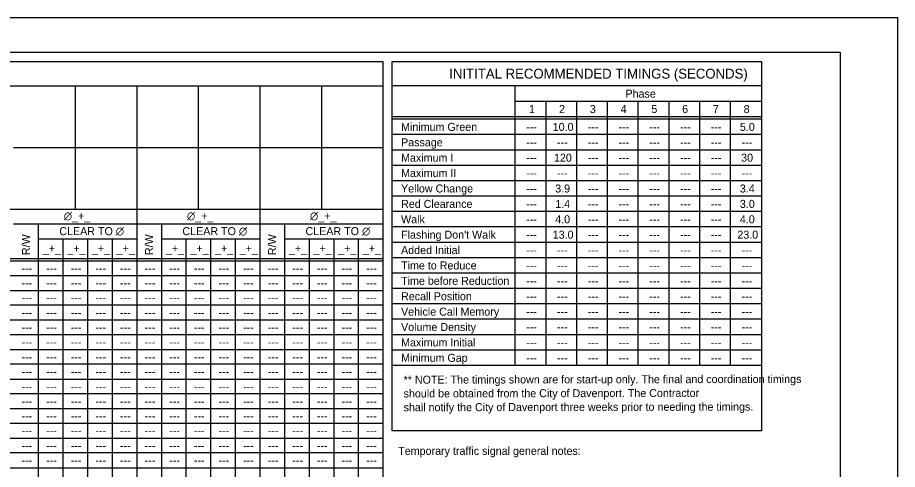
# Model space of a CAD drawing. Extents: x 10040 to 81668, y 7194 to 11018.
# Drawn here: x 11931 to 13360, y 9266 to 10000 of the extents above; entities that cross this region are included whole.
import ezdxf

# ---------------------------------------------------------------- set-up
doc = ezdxf.new("R2010")
doc.units = 0
for name, color, linetype in [('dsnCellElements', 7, 'Continuous'), ('dsnStdTable', 7, 'Continuous'), ('Level 3', 7, 'Continuous'), ('Level 4', 7, 'Continuous'), ('wetSpecialNote', 7, 'Continuous')]:
    doc.layers.add(name, color=color, linetype=linetype)

msp = doc.modelspace()

# ---------------------------------------------------------------- linework, layer by layer
at = {"layer": 'dsnCellElements'}
msp.add_lwpolyline([(10039.6, 10000), (13360.5, 10000), (13360.5, 7806.6), (10039.6, 7806.6)], close=True, dxfattribs=at)
at = {"layer": 'Level 3'}
msp.add_lwpolyline([(10132.5, 9944), (13267.5, 9944), (13267.5, 7924), (10132.5, 7924)], close=True, dxfattribs=at)
msp.add_lwpolyline([(10132.5, 9944), (13267.5, 9944), (13267.5, 7924), (10132.5, 7924)], close=True, dxfattribs=at)
at = {"layer": 'Level 4'}
for p, q in [((10664.5, 9889), (12524.5, 9889)), ((12124.5, 9889), (12124.5, 8885)), ((12124.5, 9889), (12124.5, 8885)), ((12324.5, 9889), (12324.5, 8885)), ((12324.5, 9889), (12324.5, 8885)), ((13139.5, 9889), (12539.5, 9889)), ((12739.5, 9435), (12739.5, 9889)), ((13139.5, 9864), (12739.5, 9864)), ((12789.5, 9435), (12789.5, 9864)), ((12839.5, 9435), (12839.5, 9864)), ((12889.5, 9435), (12889.5, 9864)), ((12939.5, 9435), (12939.5, 9864)), ((12989.5, 9435), (12989.5, 9864)), ((13039.5, 9435), (13039.5, 9864)), ((13089.5, 9435), (13089.5, 9864)), ((13139.5, 9835), (12539.5, 9835)), ((13139.5, 9810), (12539.5, 9810)), ((13139.5, 9785), (12539.5, 9785)), ((13139.5, 9760), (12539.5, 9760)), ((13139.5, 9735), (12539.5, 9735)), ((13139.5, 9710), (12539.5, 9710)), ((13139.5, 9685), (12539.5, 9685)), ((11964.5, 9665), (11964.5, 8885)), ((12164.5, 9665), (12164.5, 8885)), ((12364.5, 9665), (12364.5, 8885)), ((13139.5, 9660), (12539.5, 9660)), ((12004.5, 9641), (12004.5, 8885)), ((12044.5, 9641), (12044.5, 8885)), ((12084.5, 9641), (12084.5, 8885)), ((12204.5, 9641), (12204.5, 8885)), ((12244.5, 9641), (12244.5, 8885)), ((12284.5, 9641), (12284.5, 8885)), ((12404.5, 9641), (12404.5, 8885)), ((12444.5, 9641), (12444.5, 8885)), ((12484.5, 9641), (12484.5, 8885)), ((13139.5, 9635), (12539.5, 9635)), ((10664.5, 9609), (12524.5, 9609)), ((13139.5, 9610), (12539.5, 9610)), ((10664.5, 9605), (12524.5, 9605)), ((13139.5, 9585), (12539.5, 9585)), ((13139.5, 9560), (12539.5, 9560)), ((13139.5, 9535), (12539.5, 9535)), ((13139.5, 9510), (12539.5, 9510)), ((13139.5, 9485), (12539.5, 9485)), ((13139.5, 9460), (12539.5, 9460)), ((13139.5, 9435), (12539.5, 9435))]:
    msp.add_line(p, q, dxfattribs=at)
for points in [[(10664.5, 9929), (12524.5, 9929), (12524.5, 8885), (10664.5, 8885)], [(12539.5, 9929), (13139.5, 9929), (13139.5, 9329), (12539.5, 9329)]]:
    msp.add_lwpolyline(points, close=True, dxfattribs=at)
msp.add_lwpolyline([(13139.5, 9839), (12539.5, 9839)], dxfattribs=at)
at = {"layer": 'wetSpecialNote'}
for p, q in [((12024.5, 9889), (12024.5, 9689)), ((12224.5, 9889), (12224.5, 9689)), ((12424.5, 9889), (12424.5, 9689)), ((11924.5, 9789), (12124.5, 9789)), ((12124.5, 9789), (12324.5, 9789)), ((12324.5, 9789), (12524.5, 9789)), ((10664.5, 9689), (12524.5, 9689)), ((11924.5, 9665), (12124.5, 9665)), ((12124.5, 9665), (12324.5, 9665)), ((12324.5, 9665), (12524.5, 9665)), ((11964.5, 9641), (12124.5, 9641)), ((12164.5, 9641), (12324.5, 9641)), ((12364.5, 9641), (12524.5, 9641)), ((10824.5, 9581), (12524.5, 9581)), ((10824.5, 9557), (12524.5, 9557)), ((12524.5, 9533), (10824.5, 9533)), ((10824.5, 9509), (12524.5, 9509)), ((12524.5, 9485), (10664.5, 9485)), ((10824.5, 9461), (12524.5, 9461)), ((12524.5, 9437), (10824.5, 9437)), ((10824.5, 9413), (12524.5, 9413)), ((12524.5, 9389), (10824.5, 9389)), ((10664.5, 9365), (12524.5, 9365)), ((12524.5, 9341), (10824.5, 9341)), ((10824.5, 9317), (12524.5, 9317)), ((12524.5, 9293), (10824.5, 9293)), ((10824.5, 9269), (12524.5, 9269))]:
    msp.add_line(p, q, dxfattribs=at)

# ---------------------------------------------------------------- texts
at = {"layer": 'dsnStdTable'}
for s, p in [('∅_+_', (12006, 9671.4)), ('∅_+_', (12206, 9671.4)), ('∅_+_', (12406, 9671.4)), ('_+_', (11971.8, 9618.6)), ('_+_', (12011.8, 9618.6)), ('_+_', (12051.8, 9618.6)), ('_+_', (12091.8, 9618.6)), ('_+_', (12171.8, 9618.6)), ('_+_', (12211.8, 9618.6)), ('_+_', (12251.8, 9618.6)), ('_+_', (12291.8, 9618.6)), ('_+_', (12371.8, 9618.6)), ('_+_', (12411.8, 9618.6)), ('_+_', (12451.8, 9618.6)), ('_+_', (12491.8, 9618.6)), ('---', (11937.3, 9586.5)), ('---', (11977.3, 9586.5)), ('---', (12017.3, 9586.5)), ('---', (12057.3, 9586.5)), ('---', (12097.3, 9586.5)), ('---', (12137.3, 9586.5)), ('---', (12177.3, 9586.5)), ('---', (12217.3, 9586.5)), ('---', (12257.3, 9586.5)), ('---', (12297.3, 9586.5)), ('---', (12337.3, 9586.5)), ('---', (12377.3, 9586.5)), ('---', (12417.3, 9586.5)), ('---', (12457.3, 9586.5)), ('---', (12497.3, 9586.5)), ('---', (11937.3, 9562.5)), ('---', (11977.3, 9562.5)), ('---', (12017.3, 9562.5)), ('---', (12057.3, 9562.5)), ('---', (12097.3, 9562.5)), ('---', (12137.3, 9562.5)), ('---', (12177.3, 9562.5)), ('---', (12217.3, 9562.5)), ('---', (12257.3, 9562.5)), ('---', (12297.3, 9562.5)), ('---', (12337.3, 9562.5)), ('---', (12377.3, 9562.5)), ('---', (12417.3, 9562.5)), ('---', (12457.3, 9562.5)), ('---', (12497.3, 9562.5)), ('---', (11937.3, 9538.5)), ('---', (11977.3, 9538.5)), ('---', (12017.3, 9538.5)), ('---', (12057.3, 9538.5)), ('---', (12097.3, 9538.5)), ('---', (12137.3, 9538.5)), ('---', (12177.3, 9538.5)), ('---', (12217.3, 9538.5)), ('---', (12257.3, 9538.5)), ('---', (12297.3, 9538.5)), ('---', (12337.3, 9538.5)), ('---', (12377.3, 9538.5)), ('---', (12417.3, 9538.5)), ('---', (12457.3, 9538.5)), ('---', (12497.3, 9538.5)), ('---', (11937.3, 9514.5)), ('---', (11977.3, 9514.5)), ('---', (12017.3, 9514.5)), ('---', (12057.3, 9514.5)), ('---', (12097.3, 9514.5)), ('---', (12137.3, 9514.5)), ('---', (12177.3, 9514.5)), ('---', (12217.3, 9514.5)), ('---', (12257.3, 9514.5)), ('---', (12297.3, 9514.5)), ('---', (12337.3, 9514.5)), ('---', (12377.3, 9514.5)), ('---', (12417.3, 9514.5)), ('---', (12457.3, 9514.5)), ('---', (12497.3, 9514.5)), ('---', (11937.3, 9490.5)), ('---', (11977.3, 9490.5)), ('---', (12017.3, 9490.5)), ('---', (12057.3, 9490.5)), ('---', (12097.3, 9490.5)), ('---', (12137.3, 9490.5)), ('---', (12177.3, 9490.5)), ('---', (12217.3, 9490.5)), ('---', (12257.3, 9490.5)), ('---', (12297.3, 9490.5)), ('---', (12337.3, 9490.5)), ('---', (12377.3, 9490.5)), ('---', (12417.3, 9490.5)), ('---', (12457.3, 9490.5)), ('---', (12497.3, 9490.5)), ('---', (11937.3, 9466.5)), ('---', (11977.3, 9466.5)), ('---', (12017.3, 9466.5)), ('---', (12057.3, 9466.5)), ('---', (12097.3, 9466.5)), ('---', (12137.3, 9466.5)), ('---', (12177.3, 9466.5)), ('---', (12217.3, 9466.5)), ('---', (12257.3, 9466.5)), ('---', (12297.3, 9466.5)), ('---', (12337.3, 9466.5)), ('---', (12377.3, 9466.5)), ('---', (12417.3, 9466.5)), ('---', (12457.3, 9466.5)), ('---', (12497.3, 9466.5)), ('---', (11937.3, 9442.5)), ('---', (11977.3, 9442.5)), ('---', (12017.3, 9442.5)), ('---', (12057.3, 9442.5)), ('---', (12097.3, 9442.5)), ('---', (12137.3, 9442.5)), ('---', (12177.3, 9442.5)), ('---', (12217.3, 9442.5)), ('---', (12257.3, 9442.5)), ('---', (12297.3, 9442.5)), ('---', (12337.3, 9442.5)), ('---', (12377.3, 9442.5)), ('---', (12417.3, 9442.5)), ('---', (12457.3, 9442.5)), ('---', (12497.3, 9442.5)), ('---', (11937.3, 9418.5)), ('---', (11977.3, 9418.5)), ('---', (12017.3, 9418.5)), ('---', (12057.3, 9418.5)), ('---', (12097.3, 9418.5)), ('---', (12137.3, 9418.5)), ('---', (12177.3, 9418.5)), ('---', (12217.3, 9418.5)), ('---', (12257.3, 9418.5)), ('---', (12297.3, 9418.5)), ('---', (12337.3, 9418.5)), ('---', (12377.3, 9418.5)), ('---', (12417.3, 9418.5)), ('---', (12457.3, 9418.5)), ('---', (12497.3, 9418.5)), ('---', (11937.3, 9394.5)), ('---', (11977.3, 9394.5)), ('---', (12017.3, 9394.5)), ('---', (12057.3, 9394.5)), ('---', (12097.3, 9394.5)), ('---', (12137.3, 9394.5)), ('---', (12177.3, 9394.5)), ('---', (12217.3, 9394.5)), ('---', (12257.3, 9394.5)), ('---', (12297.3, 9394.5)), ('---', (12337.3, 9394.5)), ('---', (12377.3, 9394.5)), ('---', (12417.3, 9394.5)), ('---', (12457.3, 9394.5)), ('---', (12497.3, 9394.5)), ('---', (11937.3, 9370.5)), ('---', (11977.3, 9370.5)), ('---', (12017.3, 9370.5)), ('---', (12057.3, 9370.5)), ('---', (12097.3, 9370.5)), ('---', (12137.3, 9370.5)), ('---', (12177.3, 9370.5)), ('---', (12217.3, 9370.5)), ('---', (12257.3, 9370.5)), ('---', (12297.3, 9370.5)), ('---', (12337.3, 9370.5)), ('---', (12377.3, 9370.5)), ('---', (12417.3, 9370.5)), ('---', (12457.3, 9370.5)), ('---', (12497.3, 9370.5)), ('---', (11937.3, 9346.5)), ('---', (11977.3, 9346.5)), ('---', (12017.3, 9346.5)), ('---', (12057.3, 9346.5)), ('---', (12097.3, 9346.5)), ('---', (12137.3, 9346.5)), ('---', (12177.3, 9346.5)), ('---', (12217.3, 9346.5)), ('---', (12257.3, 9346.5)), ('---', (12297.3, 9346.5)), ('---', (12337.3, 9346.5)), ('---', (12377.3, 9346.5)), ('---', (12417.3, 9346.5)), ('---', (12457.3, 9346.5)), ('---', (12497.3, 9346.5)), ('---', (11937.3, 9322.5)), ('---', (11977.3, 9322.5)), ('---', (12017.3, 9322.5)), ('---', (12057.3, 9322.5)), ('---', (12097.3, 9322.5)), ('---', (12137.3, 9322.5)), ('---', (12177.3, 9322.5)), ('---', (12217.3, 9322.5)), ('---', (12257.3, 9322.5)), ('---', (12297.3, 9322.5)), ('---', (12337.3, 9322.5)), ('---', (12377.3, 9322.5)), ('---', (12417.3, 9322.5)), ('---', (12457.3, 9322.5)), ('---', (12497.3, 9322.5)), ('---', (11937.3, 9298.5)), ('---', (11977.3, 9298.5)), ('---', (12017.3, 9298.5)), ('---', (12057.3, 9298.5)), ('---', (12097.3, 9298.5)), ('---', (12137.3, 9298.5)), ('---', (12177.3, 9298.5)), ('---', (12217.3, 9298.5)), ('---', (12257.3, 9298.5)), ('---', (12297.3, 9298.5)), ('---', (12337.3, 9298.5)), ('---', (12377.3, 9298.5)), ('---', (12417.3, 9298.5)), ('---', (12457.3, 9298.5)), ('---', (12497.3, 9298.5)), ('---', (11937.3, 9274.5)), ('---', (11977.3, 9274.5)), ('---', (12017.3, 9274.5)), ('---', (12057.3, 9274.5)), ('---', (12097.3, 9274.5)), ('---', (12137.3, 9274.5)), ('---', (12177.3, 9274.5)), ('---', (12217.3, 9274.5)), ('---', (12257.3, 9274.5)), ('---', (12297.3, 9274.5)), ('---', (12337.3, 9274.5)), ('---', (12377.3, 9274.5)), ('---', (12417.3, 9274.5)), ('---', (12457.3, 9274.5)), ('---', (12497.3, 9274.5))]:
    msp.add_text(s, height=13, dxfattribs=at).set_placement(p)
at = {"layer": 'Level 4'}
for s, height, p in [('INITITAL RECOMMENDED TIMINGS (SECONDS)', 16, (12632.3, 9901)), ('Phase', 13, (12918.7, 9870)), ('1', 13, (12761.7, 9845)), ('2', 13, (12810.7, 9845)), ('3', 13, (12860.7, 9845)), ('4', 13, (12910.7, 9845)), ('5', 13, (12960.7, 9845)), ('6', 13, (13010.7, 9845)), ('7', 13, (13060.7, 9845)), ('8', 13, (13110.7, 9845)), ('Minimum Green', 13, (12554, 9816)), ('---', 13, (12757.3, 9816)), ('10.0', 13, (12800.4, 9816)), ('---', 13, (12857.3, 9816)), ('---', 13, (12907.3, 9816)), ('---', 13, (12957.3, 9816)), ('---', 13, (13007.3, 9816)), ('---', 13, (13057.3, 9816)), ('5.0', 13, (13104.5, 9816)), ('Passage', 13, (12554, 9791)), ('---', 13, (12757.3, 9791)), ('---', 13, (12807.3, 9791)), ('---', 13, (12857.3, 9791)), ('---', 13, (12907.3, 9791)), ('---', 13, (12957.3, 9791)), ('---', 13, (13007.3, 9791)), ('---', 13, (13057.3, 9791)), ('---', 13, (13107.3, 9791)), ('Maximum I', 13, (12554, 9766)), ('120', 13, (12802.4, 9766)), ('30', 13, (13106.6, 9766)), ('---', 13, (12757.3, 9766)), ('---', 13, (12857.3, 9766)), ('---', 13, (12907.3, 9766)), ('---', 13, (12957.3, 9766)), ('---', 13, (13007.3, 9766)), ('---', 13, (13057.3, 9766)), ('Maximum II', 13, (12554, 9741)), ('---', 13, (12757.3, 9741)), ('---', 13, (12807.3, 9741)), ('---', 13, (12857.3, 9741)), ('---', 13, (12907.3, 9741)), ('---', 13, (12957.3, 9741)), ('---', 13, (13007.3, 9741)), ('---', 13, (13057.3, 9741)), ('---', 13, (13107.3, 9741)), ('Yellow Change', 13, (12554, 9716)), ('---', 13, (12757.3, 9716)), ('3.9', 13, (12804.5, 9716)), ('---', 13, (12857.3, 9716)), ('---', 13, (12907.3, 9716)), ('---', 13, (12957.3, 9716)), ('---', 13, (13007.3, 9716)), ('---', 13, (13057.3, 9716)), ('3.4', 13, (13104.5, 9716)), ('Red Clearance', 13, (12554, 9691)), ('---', 13, (12757.3, 9691)), ('1.4', 13, (12804.5, 9691)), ('---', 13, (12857.3, 9691)), ('---', 13, (12907.3, 9691)), ('---', 13, (12957.3, 9691)), ('---', 13, (13007.3, 9691)), ('---', 13, (13057.3, 9691)), ('3.0', 13, (13104.5, 9691)), ('Walk', 13, (12554, 9666)), ('4.0', 13, (12804.5, 9666)), ('4.0', 13, (13104.5, 9666)), ('---', 13, (12757.3, 9666)), ('---', 13, (12857.3, 9666)), ('---', 13, (12907.3, 9666)), ('---', 13, (12957.3, 9666)), ('---', 13, (13007.3, 9666)), ('---', 13, (13057.3, 9666)), ("Flashing Don't Walk", 13, (12554, 9641)), ('13.0', 13, (12800.4, 9641)), ('23.0', 13, (13100.4, 9641)), ('---', 13, (12757.3, 9641)), ('---', 13, (12857.3, 9641)), ('---', 13, (12907.3, 9641)), ('---', 13, (12957.3, 9641)), ('---', 13, (13007.3, 9641)), ('---', 13, (13057.3, 9641)), ('Added Initial', 13, (12554, 9616)), ('---', 13, (12757.3, 9616)), ('---', 13, (12807.3, 9616)), ('---', 13, (12857.3, 9616)), ('---', 13, (12907.3, 9616)), ('---', 13, (12957.3, 9616)), ('---', 13, (13007.3, 9616)), ('---', 13, (13057.3, 9616)), ('---', 13, (13107.3, 9616)), ('Time to Reduce', 13, (12554, 9591)), ('---', 13, (12757.3, 9591)), ('---', 13, (12807.3, 9591)), ('---', 13, (12857.3, 9591)), ('---', 13, (12907.3, 9591)), ('---', 13, (12957.3, 9591)), ('---', 13, (13007.3, 9591)), ('---', 13, (13057.3, 9591)), ('---', 13, (13107.3, 9591)), ('Time before Reduction', 13, (12554, 9566)), ('---', 13, (12757.3, 9566)), ('---', 13, (12807.3, 9566)), ('---', 13, (12857.3, 9566)), ('---', 13, (12907.3, 9566)), ('---', 13, (12957.3, 9566)), ('---', 13, (13007.3, 9566)), ('---', 13, (13057.3, 9566)), ('---', 13, (13107.3, 9566)), ('Recall Position', 13, (12554, 9541)), ('---', 13, (12757.3, 9541)), ('---', 13, (12807.3, 9541)), ('---', 13, (12857.3, 9541)), ('---', 13, (12907.3, 9541)), ('---', 13, (12957.3, 9541)), ('---', 13, (13007.3, 9541)), ('---', 13, (13057.3, 9541)), ('---', 13, (13107.3, 9541)), ('Vehicle Call Memory', 13, (12554, 9516)), ('---', 13, (12757.3, 9516)), ('---', 13, (12807.3, 9516)), ('---', 13, (12857.3, 9516)), ('---', 13, (12907.3, 9516)), ('---', 13, (12957.3, 9516)), ('---', 13, (13007.3, 9516)), ('---', 13, (13057.3, 9516)), ('---', 13, (13107.3, 9516)), ('Volume Density', 13, (12554, 9491)), ('---', 13, (12757.3, 9491)), ('---', 13, (12807.3, 9491)), ('---', 13, (12857.3, 9491)), ('---', 13, (12907.3, 9491)), ('---', 13, (12957.3, 9491)), ('---', 13, (13007.3, 9491)), ('---', 13, (13057.3, 9491)), ('---', 13, (13107.3, 9491)), ('Maximum Initial', 13, (12554, 9466)), ('---', 13, (12757.3, 9466)), ('---', 13, (12807.3, 9466)), ('---', 13, (12857.3, 9466)), ('---', 13, (12907.3, 9466)), ('---', 13, (12957.3, 9466)), ('---', 13, (13007.3, 9466)), ('---', 13, (13057.3, 9466)), ('---', 13, (13107.3, 9466)), ('Minimum Gap', 13, (12554, 9441)), ('---', 13, (12757.3, 9441)), ('---', 13, (12807.3, 9441)), ('---', 13, (12857.3, 9441)), ('---', 13, (12907.3, 9441)), ('---', 13, (12957.3, 9441)), ('---', 13, (13007.3, 9441)), ('---', 13, (13057.3, 9441)), ('---', 13, (13107.3, 9441))]:
    msp.add_text(s, height=height, dxfattribs=at).set_placement(p)
at = {"layer": 'wetSpecialNote'}
for p in [(11998.7, 9646.7), (12198.7, 9646.7), (12398.7, 9646.7)]:
    msp.add_text('CLEAR TO ∅', height=13, dxfattribs=at).set_placement(p)
for s, rotation, p in [('R/W', 90, (11951, 9614.3)), ('R/W', 90, (12151, 9614.3)), ('R/W', 90, (12351, 9614.3)), ('** NOTE: The timings shown are for start-up only. The final and coordination timings', 0.102, (12558.1, 9405.5)), ('should be obtained from the City of Davenport. The Contractor', 0.102, (12558.1, 9383.1)), ('shall notify the City of Davenport three weeks prior to needing the timings.', 0.102, (12558.1, 9360.7)), ('Temporary traffic signal general notes:', 360, (12549.4, 9289.9))]:
    msp.add_text(s, height=13, rotation=rotation, dxfattribs=at).set_placement(p)

doc.saveas('drawing.dxf')
